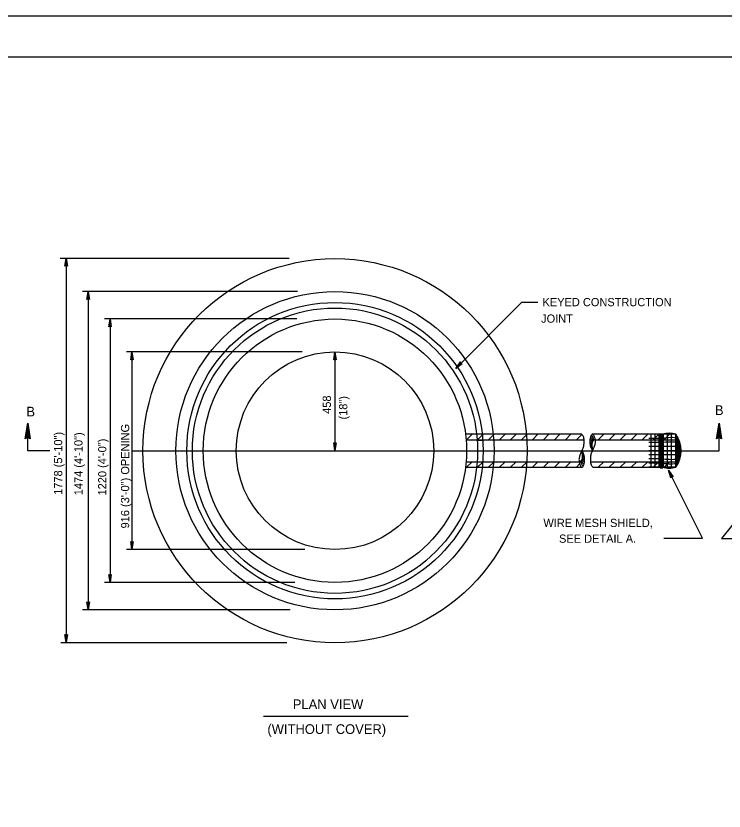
# Model space of a CAD drawing. Extents: x 638443 to 639347, y 298405 to 298999.
# Drawn here: x 638749 to 639007.2, y 298709.2 to 298999 of the extents above; entities that cross this region are included whole.
import ezdxf

# ---------------------------------------------------------------- set-up
doc = ezdxf.new("R2010")
doc.units = 0
for name, color, linetype in [('1', 7, 'Continuous'), ('2', 7, 'Continuous'), ('3', 7, 'Continuous'), ('PLT-BNDY', 7, 'Continuous')]:
    doc.layers.add(name, color=color, linetype=linetype)

msp = doc.modelspace()

# ---------------------------------------------------------------- linework, layer by layer
at = {"layer": '1'}
msp.add_lwpolyline([(639268.31, 298419.95), (639268.31, 298983.95), (638482.31, 298983.95), (638482.31, 298419.95), (639268.31, 298419.95), (639268.31, 298446.31), (639068.31, 298446.31), (639068.31, 298510.99), (639268.31, 298510.99), (639268.31, 298539.95), (639068.31, 298539.95), (639068.31, 298419.95), (639147.11, 298419.95), (639147.11, 298446.31), (639147.11, 298419.95), (639224.11, 298419.95), (639224.11, 298446.31), (639224.11, 298434), (639268.31, 298434)], dxfattribs=at)
at = {"layer": '2'}
for p, q in [((638765.2, 298910.63), (638848.63, 298910.63)), ((638767.34, 298910.63), (638767.34, 298770.63)), ((638773.34, 298898.63), (638851.69, 298898.63)), ((638775.34, 298898.5), (638775.34, 298782.5)), ((638933.34, 298894.63), (638939.34, 298894.63)), ((638781.34, 298888.63), (638851.49, 298888.63)), ((638783.34, 298888.5), (638783.34, 298792.5)), ((638789.34, 298876.63), (638853.32, 298876.63)), ((638791.34, 298876.5), (638791.34, 298804.5)), ((638865.34, 298876.5), (638865.34, 298840.5)), ((639005.34, 298840.5), (639005.34, 298850.5)), ((638913.34, 298844.5), (638915.34, 298846.5)), ((638923.26, 298846.5), (638913.34, 298846.5)), ((638913.34, 298844.5), (638956, 298844.5)), ((638917.34, 298844.5), (638919.34, 298846.5)), ((638921.34, 298844.5), (638923.34, 298846.5)), ((638955.29, 298846.5), (638923.26, 298846.5)), ((638925.34, 298844.5), (638927.34, 298846.5)), ((638929.34, 298844.5), (638931.34, 298846.5)), ((638933.34, 298844.5), (638935.34, 298846.5)), ((638937.34, 298844.5), (638939.34, 298846.5)), ((638941.34, 298844.5), (638943.34, 298846.5)), ((638945.34, 298844.5), (638947.34, 298846.5)), ((638949.34, 298844.5), (638951.34, 298846.5)), ((638953.34, 298844.5), (638955.29, 298846.45)), ((638989.54, 298846.5), (638959.3, 298846.5)), ((638959.3, 298846.46), (638959.34, 298846.5)), ((638960.34, 298844.5), (638989.54, 298844.5)), ((638961.34, 298844.5), (638963.34, 298846.5)), ((638965.34, 298844.5), (638967.34, 298846.5)), ((638969.34, 298844.5), (638971.34, 298846.5)), ((638973.34, 298844.5), (638975.34, 298846.5)), ((638977.34, 298844.5), (638979.34, 298846.5)), ((638989.54, 298846.5), (638979.77, 298846.5)), ((638984.77, 298845), (638979.79, 298845)), ((638980.54, 298834.5), (638980.54, 298846.5)), ((638981.34, 298844.5), (638983.34, 298846.5)), ((638982.04, 298834.5), (638982.04, 298846.5)), ((638983.54, 298834.5), (638983.54, 298846.5)), ((638983.94, 298834.29), (638983.94, 298846.67)), ((638983.94, 298846.67), (638984.8, 298846.67)), ((638983.99, 298834.29), (638983.99, 298846.67)), ((638984.05, 298834.29), (638984.05, 298846.67)), ((638984.12, 298834.29), (638984.12, 298846.67)), ((638984.18, 298834.29), (638984.18, 298846.67)), ((638984.24, 298834.29), (638984.24, 298846.67)), ((638984.3, 298834.29), (638984.3, 298846.67)), ((638984.37, 298834.29), (638984.37, 298846.67)), ((638984.43, 298834.29), (638984.43, 298846.67)), ((638984.49, 298834.29), (638984.49, 298846.67)), ((638984.55, 298834.29), (638984.55, 298846.67)), ((638984.61, 298834.29), (638984.61, 298846.67)), ((638984.68, 298834.29), (638984.68, 298846.67)), ((638984.74, 298834.29), (638984.74, 298846.67)), ((638984.8, 298834.29), (638984.8, 298846.67)), ((638985.04, 298834.5), (638985.04, 298846.5)), ((638985.34, 298844.5), (638987.34, 298846.5)), ((638986.54, 298834.15), (638986.54, 298846.84)), ((638988.04, 298834.19), (638988.04, 298846.81)), ((638989.54, 298834.5), (638989.54, 298846.5)), ((638989.54, 298834.5), (638989.54, 298846.5)), ((638919.34, 298844.24), (638917.34, 298844.24)), ((638985.05, 298843.5), (638979.7, 298843.5)), ((638991.43, 298842), (638979.77, 298842)), ((638791.34, 298840.5), (639004.53, 298840.5)), ((638991.54, 298840.5), (638979.73, 298840.5)), ((638991.43, 298839), (638979.75, 298839)), ((638989.54, 298840.5), (638989.54, 298840.5)), ((638989.54, 298840.5), (638989.54, 298840.5)), ((638989.94, 298840.5), (638989.94, 298840.5)), ((638990.34, 298840.5), (638990.34, 298840.5)), ((638990.74, 298840.5), (638990.74, 298840.5)), ((638991.14, 298840.5), (638991.14, 298840.5)), ((638991.54, 298840.5), (638991.54, 298840.5)), ((638995.34, 298840.5), (639005.34, 298840.5)), ((638913.34, 298834.5), (638915.34, 298836.5)), ((638913.34, 298836.5), (638954.36, 298836.5)), ((638917.34, 298834.5), (638919.34, 298836.5)), ((638921.34, 298834.5), (638923.34, 298836.5)), ((638925.34, 298834.5), (638927.34, 298836.5)), ((638929.34, 298834.5), (638931.34, 298836.5)), ((638933.34, 298834.5), (638935.34, 298836.5)), ((638937.34, 298834.5), (638939.34, 298836.5)), ((638941.34, 298834.5), (638943.34, 298836.5)), ((638945.34, 298834.5), (638947.34, 298836.5)), ((638949.34, 298834.5), (638951.34, 298836.5)), ((638958.74, 298836.5), (638989.54, 298836.5)), ((638959.3, 298836.46), (638959.34, 298836.5)), ((638961.34, 298834.5), (638963.34, 298836.5)), ((638965.34, 298834.5), (638967.34, 298836.5)), ((638969.34, 298834.5), (638971.34, 298836.5)), ((638973.34, 298834.5), (638975.34, 298836.5)), ((638977.34, 298834.5), (638979.34, 298836.5)), ((638984.95, 298836), (638979.75, 298836)), ((638985.05, 298837.5), (638979.79, 298837.5)), ((638981.34, 298834.5), (638983.34, 298836.5)), ((638985.34, 298834.5), (638987.34, 298836.5)), ((638913.34, 298834.5), (638923.26, 298834.5)), ((638923.26, 298834.5), (638955.29, 298834.5)), ((638953.34, 298834.5), (638954.52, 298835.68)), ((638959.3, 298834.5), (638989.54, 298834.5)), ((638989.54, 298834.5), (638979.75, 298834.5)), ((638983.94, 298834.29), (638984.8, 298834.29)), ((638999.27, 298808.64), (638986.89, 298833.4)), ((638985.24, 298808.64), (638999.27, 298808.64)), ((638789.34, 298804.63), (638854.34, 298804.63)), ((638781.34, 298792.63), (638850.67, 298792.63)), ((638773.34, 298782.63), (638849.04, 298782.63)), ((638765.34, 298770.63), (638847.81, 298770.63)), ((638839.26, 298743.72), (638892.02, 298743.72))]:
    msp.add_line(p, q, dxfattribs=at)
for points in [[(638767, 298907.91), (638767.2, 298908.01), (638767.34, 298910.63), (638767, 298907.91), (638766.88, 298907.77), (638767.34, 298910.63), (638767.47, 298908.01), (638767.67, 298907.91), (638767.34, 298910.63), (638767.8, 298907.77), (638767.67, 298907.91)], [(638775, 298895.78), (638775.2, 298895.88), (638775.34, 298898.5), (638775, 298895.78), (638774.88, 298895.64), (638775.34, 298898.5), (638775.47, 298895.88), (638775.67, 298895.79), (638775.34, 298898.5), (638775.8, 298895.64), (638775.67, 298895.79)], [(638783, 298885.78), (638783.2, 298885.88), (638783.34, 298888.5), (638783, 298885.78), (638782.88, 298885.64), (638783.34, 298888.5), (638783.47, 298885.88), (638783.67, 298885.79), (638783.34, 298888.5), (638783.8, 298885.64), (638783.67, 298885.79)], [(638791, 298873.78), (638791.2, 298873.88), (638791.34, 298876.5), (638791, 298873.78), (638790.88, 298873.64), (638791.34, 298876.5), (638791.47, 298873.88), (638791.67, 298873.79), (638791.34, 298876.5), (638791.8, 298873.64), (638791.67, 298873.79)], [(638865, 298873.78), (638865.2, 298873.88), (638865.34, 298876.5), (638865, 298873.78), (638864.88, 298873.64), (638865.34, 298876.5), (638865.47, 298873.88), (638865.67, 298873.79), (638865.34, 298876.5), (638865.8, 298873.64), (638865.67, 298873.79)], [(639004.66, 298845.05), (639005.05, 298845.26), (639005.34, 298850.5), (639004.66, 298845.05), (639004.42, 298844.77), (639005.34, 298850.5), (639005.6, 298845.26), (639005.99, 298845.07), (639005.34, 298850.5), (639006.25, 298844.77), (639005.99, 298845.07)], [(638987.81, 298830.81), (638987.94, 298830.99), (638986.89, 298833.4), (638987.81, 298830.81), (638987.76, 298830.63), (638986.89, 298833.4), (638988.18, 298831.11), (638988.4, 298831.12), (638986.89, 298833.4), (638988.58, 298831.04), (638988.4, 298831.12)], [(639010.25, 298832.5), (639010.25, 298818.5), (639014.25, 298818.5), (639006.25, 298808.5), (639010.25, 298808.5), (639010.25, 298794.5)], [(638791.68, 298807.23), (638791.49, 298807.12), (638791.34, 298804.5), (638791.68, 298807.23), (638791.8, 298807.37), (638791.34, 298804.5), (638791.21, 298807.12), (638791.02, 298807.22), (638791.34, 298804.5), (638790.89, 298807.37), (638791.02, 298807.22)], [(638783.68, 298795.23), (638783.49, 298795.12), (638783.34, 298792.5), (638783.68, 298795.23), (638783.8, 298795.37), (638783.34, 298792.5), (638783.21, 298795.12), (638783.02, 298795.22), (638783.34, 298792.5), (638782.89, 298795.37), (638783.02, 298795.22)], [(638775.68, 298785.23), (638775.49, 298785.12), (638775.34, 298782.5), (638775.68, 298785.23), (638775.8, 298785.37), (638775.34, 298782.5), (638775.21, 298785.12), (638775.02, 298785.22), (638775.34, 298782.5), (638774.89, 298785.37), (638775.02, 298785.22)], [(638767.68, 298773.35), (638767.49, 298773.25), (638767.34, 298770.63), (638767.68, 298773.35), (638767.8, 298773.49), (638767.34, 298770.63), (638767.21, 298773.25), (638767.02, 298773.35), (638767.34, 298770.63), (638766.89, 298773.49), (638767.02, 298773.35)]]:
    msp.add_lwpolyline(points, dxfattribs=at)
for radius in [70, 58, 54, 52, 48, 36]:
    msp.add_circle((638865.34, 298840.5), radius, dxfattribs=at)
for centre, radius, start, end in [((638957.99, 298843.97), 1.37, 2.757, 70.3813), ((638957.79, 298844.48), 1.85, 354.8555, 59.6708), ((638987.66, 298830.17), 15.1, 79.266, 101.0155), ((638987.11, 298838.67), 8.18, 72.7594, 106.3688), ((638981.54, 298840.5), 10, 323.1301, 36.8699), ((638979.09, 298840.5), 12.05, 330.1372, 29.8628), ((638975.14, 298840.5), 15.6, 337.3801, 22.6199), ((638967.44, 298840.5), 22.9, 344.8107, 15.1893), ((638964.43, 298840.5), 25.51, 349.8408, 10.1592), ((638958.62, 298843.16), 0.422, 10.9894, 140.8654), ((638958.49, 298843.67), 0.654, 350.3069, 105.1317), ((638958.66, 298842.76), 0.329, 8.8886, 171.1114), ((638958.71, 298842.26), 0.286, 14.4815, 191.8386), ((638958.76, 298841.91), 0.202, 26.1102, 221.1114), ((638958.88, 298841.5), 0.197, 346.8875, 261.2044), ((638988.05, 298813.04), 30.62, 84.3259, 95.6361), ((638955.53, 298839.97), 0.121, 136.6855, 79.5583), ((638955.71, 298839.5), 0.197, 166.8875, 81.2044), ((638955.88, 298838.75), 0.286, 194.4815, 11.8386), ((638955.83, 298839.1), 0.202, 206.1102, 41.1114), ((638959.06, 298841.04), 0.121, 316.6855, 259.5583), ((638956.8, 298836.53), 1.85, 174.8555, 239.6708), ((638956.6, 298837.03), 1.37, 182.757, 250.3813), ((638956.1, 298837.34), 0.654, 170.3069, 285.1317), ((638955.96, 298837.85), 0.422, 190.9894, 320.8654), ((638955.93, 298838.24), 0.329, 188.8886, 351.1114), ((638987.66, 298850.84), 15.1, 258.9845, 280.734), ((638988.05, 298867.97), 30.62, 264.3639, 275.6741), ((638987.11, 298842.32), 8.18, 253.6312, 287.2406)]:
    msp.add_arc(centre, radius, start, end, dxfattribs=at)
for points in [[(638955.29, 298846.5), (638955.66, 298846.08), (638955.88, 298845.45), (638956, 298844.67), (638956.01, 298843.96), (638956, 298843.03), (638955.94, 298842.35), (638955.81, 298841.64), (638955.59, 298841.03), (638955.27, 298840.49), (638954.98, 298839.71), (638954.77, 298839.16), (638954.53, 298838.47), (638954.38, 298837.93), (638954.29, 298837.32), (638954.31, 298836.82), (638954.36, 298836.3), (638954.53, 298835.8), (638954.73, 298835.22), (638954.98, 298834.82), (638955.29, 298834.5), (638955.66, 298834.65), (638955.87, 298834.93), (638956, 298835.3), (638956.16, 298835.69), (638956.26, 298836.23), (638956.35, 298836.78), (638956.35, 298837.25), (638956.33, 298837.71), (638956.26, 298838.21), (638956.2, 298838.67), (638956.07, 298839.1), (638955.88, 298839.57), (638955.64, 298839.92), (638955.55, 298840.16), (638955.33, 298840.49)], [(638959.3, 298834.5), (638958.93, 298834.93), (638958.71, 298835.56), (638958.59, 298836.34), (638958.58, 298837.04), (638958.59, 298837.97), (638958.65, 298838.66), (638958.78, 298839.36), (638959, 298839.97), (638959.32, 298840.51), (638959.61, 298841.29), (638959.82, 298841.85), (638960.06, 298842.53), (638960.21, 298843.07), (638960.3, 298843.68), (638960.28, 298844.18), (638960.23, 298844.7), (638960.06, 298845.2), (638959.86, 298845.78), (638959.61, 298846.19), (638959.3, 298846.5), (638958.93, 298846.35), (638958.72, 298846.08), (638958.59, 298845.71), (638958.43, 298845.32), (638958.33, 298844.78), (638958.24, 298844.22), (638958.24, 298843.76), (638958.26, 298843.29), (638958.33, 298842.79), (638958.39, 298842.33), (638958.52, 298841.9), (638958.71, 298841.44), (638958.95, 298841.09), (638959.04, 298840.85), (638959.26, 298840.51)], [(638960.23, 298844.5), (638959.87, 298844.44), (638959.61, 298844.28), (638959.35, 298843.96), (638959.19, 298843.68), (638959.04, 298843.24), (638959, 298842.76), (638958.98, 298842.35), (638959, 298841.98), (638959.08, 298841.53), (638959.13, 298841.18), (638959.21, 298840.92), (638959.32, 298840.55)], [(638954.36, 298836.5), (638954.72, 298836.56), (638954.98, 298836.73), (638955.24, 298837.04), (638955.4, 298837.32), (638955.55, 298837.77), (638955.59, 298838.25), (638955.61, 298838.66), (638955.59, 298839.03), (638955.51, 298839.47), (638955.46, 298839.82), (638955.38, 298840.08), (638955.27, 298840.46)]]:
    msp.add_spline(points, degree=3, dxfattribs=at)
at = {"layer": '3'}
for p, q in [((638909.34, 298870.5), (638933.34, 298894.5)), ((638753.34, 298840.5), (638753.34, 298850.5)), ((638761.34, 298840.5), (638753.34, 298840.5))]:
    msp.add_line(p, q, dxfattribs=at)
for points in [[(638911.51, 298872.19), (638911.3, 298872.25), (638909.34, 298870.5), (638911.51, 298872.19), (638911.69, 298872.2), (638909.34, 298870.5), (638911.1, 298872.45), (638911.03, 298872.65), (638909.34, 298870.5), (638911.05, 298872.85), (638911.03, 298872.65)], [(638752.66, 298845.05), (638753.05, 298845.26), (638753.34, 298850.5), (638752.66, 298845.05), (638752.42, 298844.77), (638753.34, 298850.5), (638753.6, 298845.26), (638753.99, 298845.07), (638753.34, 298850.5), (638754.25, 298844.77), (638753.99, 298845.07)], [(638865.68, 298843.23), (638865.49, 298843.12), (638865.34, 298840.5), (638865.68, 298843.23), (638865.8, 298843.37), (638865.34, 298840.5), (638865.21, 298843.12), (638865.02, 298843.22), (638865.34, 298840.5), (638864.89, 298843.37), (638865.02, 298843.22)]]:
    msp.add_lwpolyline(points, dxfattribs=at)
at = {"layer": 'PLT-BNDY'}
msp.add_lwpolyline([(638443.31, 298998.95), (639284.31, 298998.95), (639284.31, 298404.95), (638443.31, 298404.95)], close=True, dxfattribs=at)

# ---------------------------------------------------------------- texts
at = {"layer": '2'}
for s, p in [('B', (639003.84, 298853.51)), ('PLAN VIEW', (638849.96, 298746.34)), ('(WITHOUT COVER)', (638840.71, 298737.28))]:
    msp.add_text(s, height=3.53, dxfattribs=at).set_placement(p)
at = {"layer": '3'}
for s, height, p in [('KEYED CONSTRUCTION', 3, (638941, 298893.15)), ('JOINT', 3, (638940.48, 298887.14)), ('B', 3.53, (638752.84, 298852.97)), ('WIRE MESH SHIELD,', 3, (638941.31, 298812.69)), ('SEE DETAIL A.', 3, (638947.02, 298806.95))]:
    msp.add_text(s, height=height, dxfattribs=at).set_placement(p)
for s, p in [('458', (638863.86, 298853.93)), ('(18")', (638869.81, 298851.86)), ('916 (3\'-0") OPENING', (638790.32, 298812.18)), ('1778 (5\'-10")', (638765.91, 298824.42)), ('1474 (4\'-10")', (638773.3, 298824.27)), ('1220 (4\'-0")', (638781.99, 298824.19))]:
    msp.add_text(s, height=3, rotation=90, dxfattribs=at).set_placement(p)

doc.saveas('drawing.dxf')
